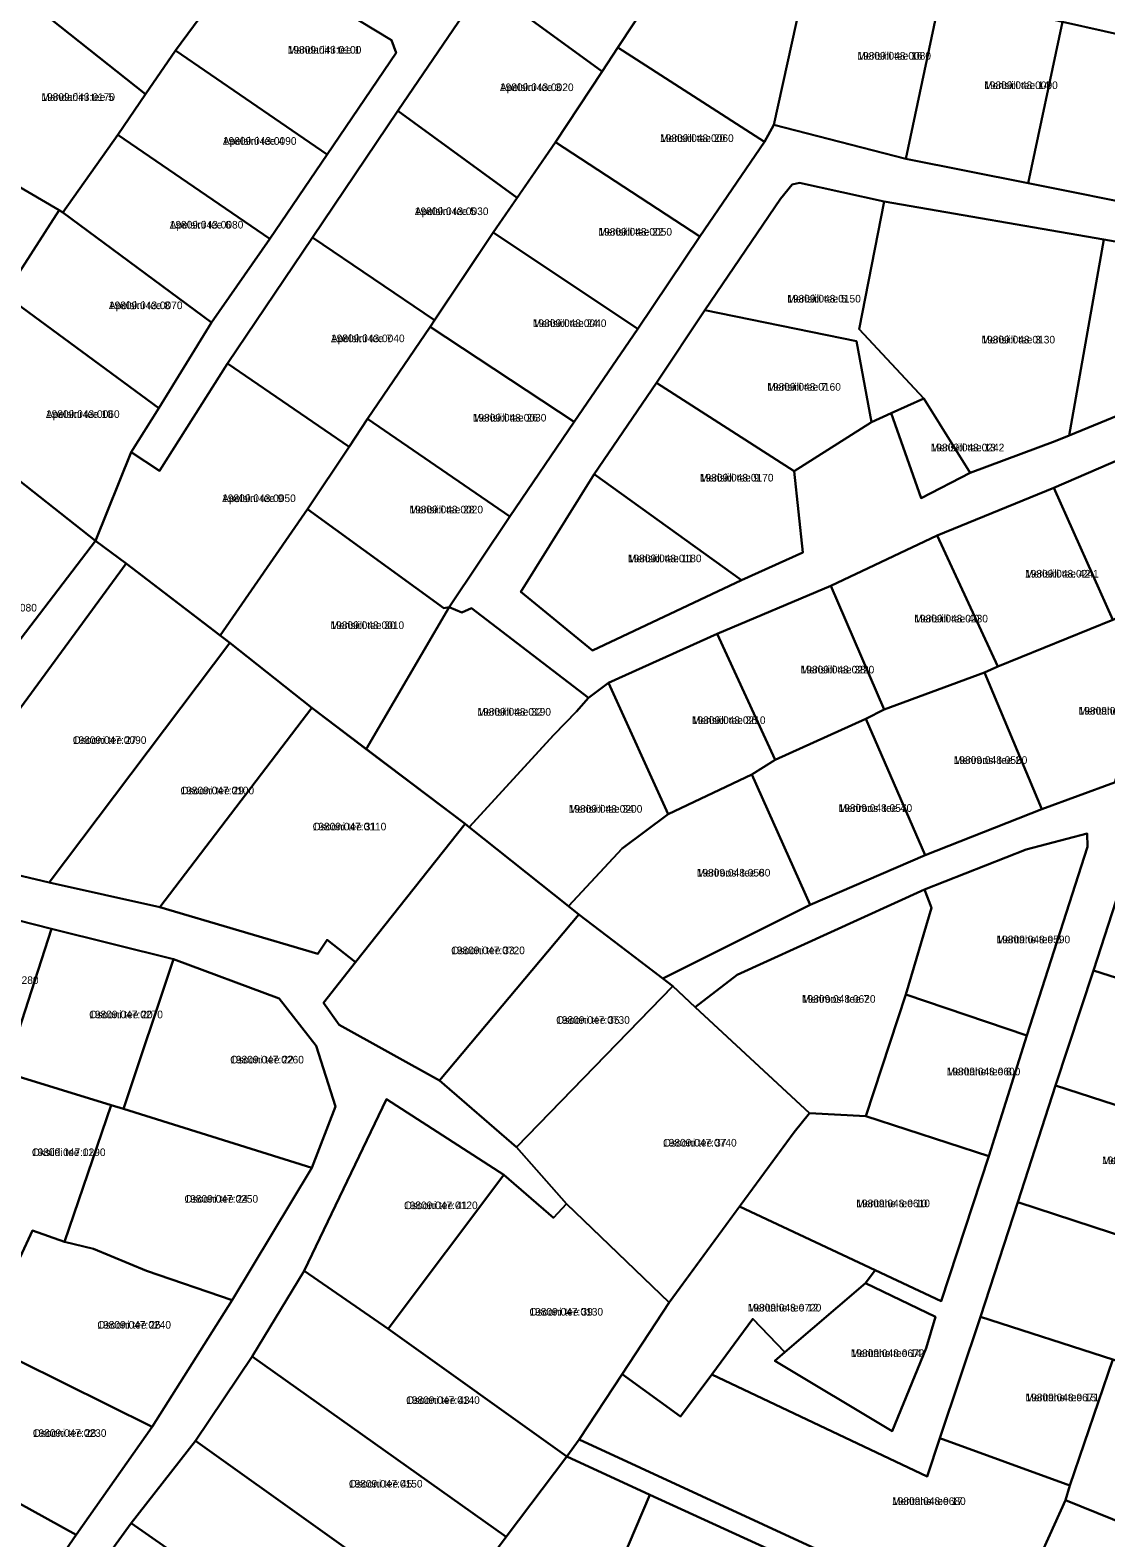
# Model space of a CAD drawing. Extents: x 516875 to 535633, y 6574491 to 6593094.
# Drawn here: x 522021.7 to 522233.5, y 6588097.9 to 6588394.7 of the extents above; entities that cross this region are included whole.
import ezdxf

# ---------------------------------------------------------------- set-up
doc = ezdxf.new("R2010")
doc.units = 0
for name, color, linetype in [('L_AADRESS', 7, 'Continuous'), ('PIIR', 7, 'Continuous'), ('TUNNUS', 7, 'Continuous')]:
    doc.layers.add(name, color=color, linetype=linetype)

msp = doc.modelspace()

# ---------------------------------------------------------------- linework, layer by layer
at = {"layer": 'PIIR'}
for points in [[(522152.8, 6588414.65), (522137.34, 6588391.3), (522134.27, 6588386.61), (522110.91, 6588403.64), (522127.24, 6588429.4)], [(522033.23, 6588412.68), (522040.61, 6588415.96), (522050.21, 6588417.4), (522064.48, 6588409.93), (522050.26, 6588390.69), (522044.38, 6588382.1), (522018.39, 6588402.82)], [(522175.18, 6588408.28), (522168.11, 6588376.06), (522166.24, 6588372.75), (522137.34, 6588391.3), (522152.8, 6588414.65)], [(522064.48, 6588409.93), (522092.78, 6588392.77), (522093.7, 6588390.23), (522080.13, 6588370.27), (522050.26, 6588390.69)], [(522200.95, 6588401.92), (522194.06, 6588369.42), (522168.11, 6588376.06), (522175.18, 6588408.28)], [(522006.88, 6588371.24), (522008.43, 6588373.57), (522002.04, 6588377.52), (522008, 6588386.5), (522004.6, 6588391.87), (522018.39, 6588402.82), (522044.38, 6588382.1), (522038.94, 6588374.15), (522028.11, 6588358.8), (522027.34, 6588359.31)], [(522094.05, 6588378.86), (522110.91, 6588403.64), (522134.27, 6588386.61), (522125.12, 6588372.66), (522117.54, 6588361.73)], [(522224.93, 6588396.36), (522218.17, 6588364.58), (522194.06, 6588369.42), (522200.95, 6588401.92)], [(522249.57, 6588390.88), (522243.06, 6588359.61), (522218.17, 6588364.58), (522224.93, 6588396.36)], [(522044.38, 6588382.1), (522050.26, 6588390.69), (522080.13, 6588370.27), (522068.88, 6588353.63), (522038.94, 6588374.15)], [(522166.24, 6588372.75), (522153.54, 6588354.12), (522125.12, 6588372.66), (522134.27, 6588386.61), (522137.34, 6588391.3)], [(522077.26, 6588353.91), (522094.05, 6588378.86), (522117.54, 6588361.73), (522112.82, 6588354.92), (522101.27, 6588337.6)], [(522038.94, 6588374.15), (522068.88, 6588353.63), (522057.37, 6588337.19), (522028.11, 6588358.8)], [(522153.54, 6588354.12), (522141.28, 6588335.9), (522112.82, 6588354.92), (522125.12, 6588372.66)], [(521982.14, 6588335.38), (522004.99, 6588368.24), (522006.88, 6588371.24), (522027.34, 6588359.31), (522016.7, 6588342.59), (522002.12, 6588319.68)], [(522132.7, 6588307.34), (522118.27, 6588284.12), (522132.35, 6588272.62), (522161.72, 6588286.42), (522173.79, 6588291.9), (522172.07, 6588307.93), (522187.34, 6588317.56), (522191.17, 6588319.3), (522197.1, 6588302.61), (522206.77, 6588307.61), (522223.48, 6588313.81), (522226.22, 6588314.93), (522260.43, 6588328.94), (522264.83, 6588347.96), (522233.05, 6588353.51), (522189.84, 6588360.99), (522173.11, 6588364.66), (522171.69, 6588364.32), (522169.41, 6588361.54), (522154.49, 6588339.57), (522144.96, 6588325.31)], [(522169.41, 6588361.54), (522171.69, 6588364.32), (522173.11, 6588364.66), (522189.84, 6588360.99), (522184.87, 6588335.85), (522197.6, 6588322.22), (522191.17, 6588319.3), (522187.34, 6588317.56), (522184.34, 6588333.53), (522154.49, 6588339.57)], [(522233.05, 6588353.51), (522226.22, 6588314.93), (522223.48, 6588313.81), (522206.77, 6588307.61), (522197.6, 6588322.22), (522184.87, 6588335.85), (522189.84, 6588360.99)], [(522027.34, 6588359.31), (522028.11, 6588358.8), (522057.37, 6588337.19), (522046.97, 6588320.29), (522016.7, 6588342.59)], [(522060.5, 6588329.11), (522077.26, 6588353.91), (522101.27, 6588337.6), (522100.44, 6588336.34), (522088.1, 6588318.24), (522084.44, 6588312.72)], [(522141.28, 6588335.9), (522128.75, 6588317.63), (522100.44, 6588336.34), (522112.82, 6588354.92)], [(522264.83, 6588347.96), (522260.43, 6588328.94), (522226.22, 6588314.93), (522233.05, 6588353.51)], [(522016.7, 6588342.59), (522046.97, 6588320.29), (522041.55, 6588311.63), (522034.49, 6588294.19), (522015.34, 6588309.29), (522002.12, 6588319.68)], [(522184.34, 6588333.53), (522187.34, 6588317.56), (522172.07, 6588307.93), (522144.96, 6588325.31), (522154.49, 6588339.57)], [(522128.75, 6588317.63), (522116.08, 6588299.01), (522088.1, 6588318.24), (522100.44, 6588336.34)], [(522041.55, 6588311.63), (522047.14, 6588308), (522060.5, 6588329.11), (522084.44, 6588312.72), (522076.28, 6588300.44), (522059.06, 6588275.58), (522040.58, 6588289.75), (522034.49, 6588294.19)], [(522172.07, 6588307.93), (522173.79, 6588291.9), (522161.72, 6588286.42), (522132.7, 6588307.34), (522144.96, 6588325.31)], [(522197.6, 6588322.22), (522206.77, 6588307.61), (522197.1, 6588302.61), (522191.17, 6588319.3)], [(522116.08, 6588299.01), (522104.18, 6588281.14), (522103.13, 6588280.96), (522076.28, 6588300.44), (522084.44, 6588312.72), (522088.1, 6588318.24)], [(522255.64, 6588313.9), (522246.62, 6588283.32), (522244.6, 6588282.7), (522234.84, 6588278.67), (522223.2, 6588304.62), (522252.05, 6588317.08)], [(522034.49, 6588294.19), (521994.15, 6588241.44), (521982.51, 6588259.22), (521982.46, 6588266.63), (522015.34, 6588309.29)], [(522132.7, 6588307.34), (522161.72, 6588286.42), (522132.35, 6588272.62), (522118.27, 6588284.12)], [(522234.84, 6588278.67), (522212.17, 6588269.45), (522200.25, 6588295.23), (522223.2, 6588304.62)], [(522103.13, 6588280.96), (522104.18, 6588281.14), (522087.84, 6588253.21), (522077.1, 6588261.34), (522061, 6588274.09), (522059.06, 6588275.58), (522076.28, 6588300.44)], [(522212.17, 6588269.45), (522209.58, 6588268.26), (522189.83, 6588260.99), (522179.31, 6588285.33), (522200.25, 6588295.23)], [(522061, 6588274.09), (522025.42, 6588226.93), (521999.1, 6588233.14), (522040.58, 6588289.75)], [(522189.83, 6588260.99), (522186.18, 6588259.15), (522168.35, 6588251.09), (522156.9, 6588275.88), (522179.31, 6588285.33)], [(522212.17, 6588269.45), (522234.84, 6588278.67), (522244.6, 6588282.7), (522246.62, 6588283.32), (522241.95, 6588268.51), (522235.19, 6588246.62), (522220.83, 6588241.4), (522209.58, 6588268.26)], [(522131.57, 6588263.27), (522129.24, 6588260.58), (522124.74, 6588256.01), (522108.13, 6588237.82), (522107.34, 6588238.45), (522087.84, 6588253.21), (522104.18, 6588281.14), (522106.68, 6588280.08), (522108.54, 6588280.91)], [(522077.1, 6588261.34), (522047.22, 6588222.1), (522025.42, 6588226.93), (522061, 6588274.09)], [(522168.35, 6588251.09), (522163.76, 6588248.18), (522147.26, 6588240.41), (522135.54, 6588266.24), (522156.9, 6588275.88)], [(522189.83, 6588260.99), (522209.58, 6588268.26), (522220.83, 6588241.4), (522197.91, 6588232.32), (522186.18, 6588259.15)], [(522147.26, 6588240.41), (522138.22, 6588233.62), (522127.64, 6588222.27), (522108.13, 6588237.82), (522124.74, 6588256.01), (522129.24, 6588260.58), (522131.57, 6588263.27), (522135.54, 6588266.24)], [(522107.34, 6588238.45), (522085.74, 6588211.23), (522080.11, 6588215.65), (522078.33, 6588212.86), (522047.22, 6588222.1), (522077.1, 6588261.34)], [(522168.35, 6588251.09), (522186.18, 6588259.15), (522197.91, 6588232.32), (522175.23, 6588222.53), (522163.76, 6588248.18)], [(522138.22, 6588233.62), (522147.26, 6588240.41), (522163.76, 6588248.18), (522175.23, 6588222.53), (522146.2, 6588208.03), (522129.68, 6588220.65), (522127.64, 6588222.27)], [(522129.68, 6588220.65), (522102.27, 6588187.96), (522082.51, 6588198.91), (522079.44, 6588203.24), (522085.74, 6588211.23), (522107.34, 6588238.45), (522108.13, 6588237.82), (522127.64, 6588222.27)], [(522217.79, 6588233.4), (522229.79, 6588236.58), (522229.82, 6588233.97), (522217.9, 6588196.82), (522194.05, 6588204.89), (522199.12, 6588221.96), (522197.78, 6588225.57)], [(522264.52, 6588225.6), (522256.75, 6588201.43), (522231.06, 6588209.59), (522239.11, 6588234.54)], [(522025.87, 6588217.8), (522016.71, 6588189.53), (522015.02, 6588189.79), (521991.75, 6588197.28), (521998.77, 6588224.68)], [(522160.84, 6588208.77), (522197.78, 6588225.57), (522199.12, 6588221.96), (522194.05, 6588204.89), (522186.19, 6588180.95), (522175.11, 6588181.52), (522152.6, 6588202.41)], [(522148.19, 6588206.51), (522117.44, 6588174.86), (522102.27, 6588187.96), (522129.68, 6588220.65)], [(522049.87, 6588211.85), (522040.05, 6588182.35), (522037.62, 6588183.1), (522016.71, 6588189.53), (522025.87, 6588217.8)], [(522070.67, 6588204.07), (522077.96, 6588194.8), (522081.76, 6588182.84), (522077.15, 6588170.76), (522040.05, 6588182.35), (522049.87, 6588211.85)], [(522256.75, 6588201.43), (522249.29, 6588178.66), (522223.53, 6588187), (522231.06, 6588209.59)], [(522175.11, 6588181.52), (522172.07, 6588177.81), (522147.45, 6588144.23), (522127.23, 6588163.69), (522117.44, 6588174.86), (522148.19, 6588206.51), (522152.6, 6588202.41)], [(522217.9, 6588196.82), (522210.4, 6588173.05), (522186.19, 6588180.95), (522194.05, 6588204.89)], [(522016.71, 6588189.53), (522037.62, 6588183.1), (522028.41, 6588156.16), (522022.09, 6588158.45), (522019.69, 6588153.15), (522006.38, 6588159.24), (522015.02, 6588189.79)], [(522114.9, 6588169.41), (522092.18, 6588139.05), (522075.63, 6588150.46), (522091.83, 6588184.31)], [(522249.29, 6588178.66), (522241.75, 6588155.97), (522238.21, 6588156.8), (522216.11, 6588164.03), (522223.53, 6588187)], [(522040.05, 6588182.35), (522077.15, 6588170.76), (522061.45, 6588144.69), (522044.54, 6588150.49), (522034.11, 6588154.83), (522028.41, 6588156.16), (522037.62, 6588183.1)], [(522186.19, 6588180.95), (522210.4, 6588173.05), (522201.03, 6588144.5), (522188.03, 6588150.64), (522161.3, 6588163.12), (522172.07, 6588177.81), (522175.11, 6588181.52)], [(522124.73, 6588160.89), (522127.23, 6588163.69), (522147.45, 6588144.23), (522138.23, 6588130.17), (522129.78, 6588117.27), (522127.32, 6588113.93), (522092.18, 6588139.05), (522114.9, 6588169.41)], [(522238.21, 6588156.8), (522241.75, 6588155.97), (522267.45, 6588147.22), (522260.42, 6588125.68), (522257.32, 6588125.93), (522234.84, 6588133), (522208.79, 6588141.4), (522216.11, 6588164.03)], [(522188.03, 6588150.64), (522186.11, 6588148.07), (522170.22, 6588134.49), (522163.95, 6588141.03), (522155.87, 6588130.09), (522149.7, 6588121.84), (522138.23, 6588130.17), (522147.45, 6588144.23), (522161.3, 6588163.12)], [(522028.41, 6588156.16), (522034.11, 6588154.83), (522044.54, 6588150.49), (522061.45, 6588144.69), (522045.71, 6588119.75), (522010.71, 6588137.12), (522018.22, 6588150), (522019.69, 6588153.15), (522022.09, 6588158.45)], [(522092.18, 6588139.05), (522127.32, 6588113.93), (522115.41, 6588098.09), (522065.34, 6588133.64), (522075.63, 6588150.46)], [(522199.93, 6588141.45), (522198.07, 6588135.24), (522191.41, 6588118.94), (522168.26, 6588132.78), (522170.22, 6588134.49), (522186.11, 6588148.07)], [(522234.84, 6588133), (522226.35, 6588108.22), (522200.79, 6588117.55), (522208.79, 6588141.4)], [(522045.71, 6588119.75), (522030.73, 6588098.49), (521999.11, 6588115.98), (522000.79, 6588119.34), (522010.71, 6588137.12)], [(522115.41, 6588098.09), (522103.31, 6588082), (522054.22, 6588117.03), (522065.34, 6588133.64)], [(522257.32, 6588125.93), (522260.42, 6588125.68), (522250.51, 6588095.21), (522225.49, 6588105.33), (522226.35, 6588108.22), (522234.84, 6588133)], [(522149.7, 6588121.84), (522155.87, 6588130.09), (522198.27, 6588109.97), (522200.79, 6588117.55), (522226.35, 6588108.22), (522225.49, 6588105.33), (522213.47, 6588078.63), (522129.78, 6588117.27), (522138.23, 6588130.17)], [(522103.31, 6588082), (522091.23, 6588066.09), (522089.56, 6588067.27), (522041.53, 6588100.82), (522054.22, 6588117.03)], [(522030.73, 6588098.49), (522015.31, 6588076.21), (521986.11, 6588096.1), (521987.51, 6588098.39), (521996.37, 6588111.18), (521999.11, 6588115.98)], [(522143.64, 6588106.38), (522126.74, 6588066.59), (522100.63, 6588077.88), (522103.31, 6588082), (522115.41, 6588098.09), (522127.32, 6588113.93)], [(522143.64, 6588106.38), (522166.8, 6588095.85), (522149.73, 6588056.5), (522126.74, 6588066.59)], [(522250.51, 6588095.21), (522253.6, 6588093.82), (522244.48, 6588064.28), (522213.47, 6588078.63), (522225.49, 6588105.33)], [(522089.56, 6588067.27), (522077.12, 6588050.77), (522030.44, 6588085.53), (522041.53, 6588100.82)]]:
    msp.add_lwpolyline(points, close=True, dxfattribs=at)
for points in [[(522110.91, 6588403.64), (522094.05, 6588378.86), (522077.26, 6588353.91), (522060.5, 6588329.11), (522047.14, 6588308), (522041.55, 6588311.63), (522046.97, 6588320.29), (522057.37, 6588337.19), (522068.88, 6588353.63), (522080.13, 6588370.27), (522093.7, 6588390.23), (522092.78, 6588392.77), (522064.48, 6588409.93)], [(522249.57, 6588390.88), (522224.93, 6588396.36)], [(522252.05, 6588317.08), (522223.2, 6588304.62), (522200.25, 6588295.23), (522179.31, 6588285.33), (522156.9, 6588275.88), (522135.54, 6588266.24), (522131.57, 6588263.27), (522108.54, 6588280.91), (522106.68, 6588280.08), (522104.18, 6588281.14), (522116.08, 6588299.01), (522128.75, 6588317.63), (522141.28, 6588335.9), (522153.54, 6588354.12), (522166.24, 6588372.75), (522168.11, 6588376.06), (522194.06, 6588369.42), (522218.17, 6588364.58), (522243.06, 6588359.61)], [(521994.15, 6588241.44), (522034.49, 6588294.19), (522040.58, 6588289.75), (521999.1, 6588233.14), (522025.42, 6588226.93), (522047.22, 6588222.1), (522078.33, 6588212.86), (522080.11, 6588215.65), (522085.74, 6588211.23), (522079.44, 6588203.24), (522082.51, 6588198.91), (522102.27, 6588187.96), (522117.44, 6588174.86), (522127.23, 6588163.69), (522124.73, 6588160.89), (522114.9, 6588169.41), (522091.83, 6588184.31), (522075.63, 6588150.46), (522065.34, 6588133.64), (522054.22, 6588117.03), (522041.53, 6588100.82), (522030.44, 6588085.53)], [(522239.11, 6588234.54), (522231.06, 6588209.59), (522223.53, 6588187), (522216.11, 6588164.03), (522208.79, 6588141.4), (522200.79, 6588117.55), (522198.27, 6588109.97), (522155.87, 6588130.09), (522163.95, 6588141.03), (522170.22, 6588134.49), (522168.26, 6588132.78), (522191.41, 6588118.94), (522198.07, 6588135.24), (522199.93, 6588141.45), (522186.11, 6588148.07), (522188.03, 6588150.64), (522201.03, 6588144.5), (522210.4, 6588173.05), (522217.9, 6588196.82), (522229.82, 6588233.97), (522229.79, 6588236.58), (522217.79, 6588233.4), (522197.78, 6588225.57), (522160.84, 6588208.77), (522152.6, 6588202.41), (522148.19, 6588206.51), (522146.2, 6588208.03), (522175.23, 6588222.53), (522197.91, 6588232.32), (522220.83, 6588241.4), (522235.19, 6588246.62)], [(522015.31, 6588076.21), (522030.73, 6588098.49), (522045.71, 6588119.75), (522061.45, 6588144.69), (522077.15, 6588170.76), (522081.76, 6588182.84), (522077.96, 6588194.8), (522070.67, 6588204.07), (522049.87, 6588211.85), (522025.87, 6588217.8), (521998.77, 6588224.68), (521965.79, 6588221.88), (521954.83, 6588217.23), (521937.53, 6588201.19), (521922.82, 6588181.22), (521909.42, 6588162.67), (521895.72, 6588144.67), (521882.77, 6588125.18), (521864.91, 6588102.09), (521893.34, 6588086.36)], [(522235.1, 6588065.06), (522212.08, 6588075.43), (522189.38, 6588085.67), (522166.8, 6588095.85), (522143.64, 6588106.38), (522127.32, 6588113.93), (522129.78, 6588117.27), (522213.47, 6588078.63), (522244.48, 6588064.28)]]:
    msp.add_lwpolyline(points, dxfattribs=at)

# ---------------------------------------------------------------- texts
at = {"layer": 'L_AADRESS'}
for s, p in [('Mandariini tee 1', (522072.37, 6588390.1)), ('Merisiili tee 16', (522184.53, 6588388.92)), ('Apelsini tee 3', (522114.16, 6588382.73)), ('Merisiili tee 14', (522209.5, 6588383.13)), ('Mandariini tee 5', (522023.86, 6588380.81)), ('Merisiili tee 20', (522145.68, 6588372.71)), ('Apelsini tee 4', (522059.6, 6588372.16)), ('Apelsini tee 5', (522097.4, 6588358.32)), ('Apelsini tee 6', (522049.13, 6588355.67)), ('Merisiili tee 22', (522133.54, 6588354.28)), ('Merisiili tee 5', (522170.72, 6588341.11)), ('Apelsini tee 8', (522037.16, 6588339.8)), ('Merisiili tee 24', (522120.63, 6588336.28)), ('Apelsini tee 7', (522080.89, 6588333.3)), ('Merisiili tee 3', (522208.96, 6588333.05)), ('Merisiili tee 7', (522166.79, 6588323.75)), ('Apelsini tee 10', (522024.77, 6588318.39)), ('Merisiili tee 26', (522108.8, 6588317.68)), ('Merisiili tee 13', (522198.97, 6588311.81)), ('Merisiili tee 9', (522153.52, 6588305.87)), ('Apelsini tee 9', (522059.46, 6588301.82)), ('Merisiili tee 28', (522096.33, 6588299.6)), ('Merisiili tee 11', (522139.35, 6588289.98)), ('Merisiili tee 42', (522217.55, 6588286.97)), ('Merisiili tee 40', (522195.74, 6588278.13)), ('Merisiili tee 30', (522080.79, 6588276.83)), ('Merisiili tee 38', (522173.36, 6588268.09)), ('Meritähe tee 4', (522228.1, 6588259.99)), ('Merisiili tee 32', (522109.71, 6588259.78)), ('Merisiili tee 36', (522151.95, 6588258.13)), ('Osooni tee 27', (522030.05, 6588254.22)), ('Meriroosi tee 2', (522203.5, 6588250.28)), ('Osooni tee 29', (522051.26, 6588244.29)), ('Merisiili tee 34', (522127.7, 6588240.67)), ('Meriroosi tee 4', (522180.83, 6588240.84)), ('Osooni tee 31', (522077.28, 6588237.19)), ('Meriroosi tee 6', (522152.91, 6588228.11)), ('Osooni tee 33', (522104.56, 6588212.82)), ('Meritähe tee 6', (522211.93, 6588214.97)), ('Meriroosi tee 7', (522173.61, 6588203.26)), ('Osooni tee 20', (522033.29, 6588200.2)), ('Osooni tee 35', (522125.23, 6588199.11)), ('Osooni tee 22', (522061.05, 6588191.31)), ('Meritähe tee 8', (522202.12, 6588188.97)), ('Osooni tee 37', (522146.27, 6588174.95)), ('Oksiidi tee 11', (522022, 6588173.08)), ('Meritähe tee 11', (522232.71, 6588171.49)), ('Osooni tee 24', (522052.04, 6588163.9)), ('Osooni tee 41', (522095.27, 6588162.63)), ('Meritähe tee 10', (522184.32, 6588163.01)), ('Osooni tee 39', (522119.96, 6588141.67)), ('Meritähe tee 12', (522162.94, 6588142.48)), ('Osooni tee 26', (522034.89, 6588139.1)), ('Meritähe tee 14', (522183.23, 6588133.51)), ('Osooni tee 43', (522095.69, 6588124.28)), ('Meritähe tee 15', (522217.63, 6588124.81)), ('Osooni tee 28', (522022.18, 6588117.8)), ('Osooni tee 45', (522084.42, 6588107.82)), ('Meritähe tee 17', (522191.36, 6588104.4))]:
    msp.add_text(s, height=1.5, dxfattribs=at).set_placement(p)
at = {"layer": 'TUNNUS'}
for s, p in [('19809:043:0100', (522072.37, 6588390.1)), ('19809:048:0080', (522184.53, 6588388.92)), ('19809:043:0020', (522114.16, 6588382.73)), ('19809:048:0090', (522209.5, 6588383.13)), ('19809:043:0170', (522023.86, 6588380.81)), ('19809:043:0090', (522059.6, 6588372.16)), ('19809:048:0060', (522145.68, 6588372.71)), ('19809:043:0030', (522097.4, 6588358.32)), ('19809:043:0080', (522049.13, 6588355.67)), ('19809:048:0050', (522133.54, 6588354.28)), ('19809:048:0150', (522170.72, 6588341.11)), ('19809:043:0070', (522037.16, 6588339.8)), ('19809:048:0040', (522120.63, 6588336.28)), ('19809:043:0040', (522080.89, 6588333.3)), ('19809:048:0130', (522208.96, 6588333.05)), ('19809:048:0160', (522166.79, 6588323.75)), ('19809:043:0060', (522024.77, 6588318.39)), ('19809:048:0030', (522108.8, 6588317.68)), ('19809:048:0242', (522198.97, 6588311.81)), ('19809:048:0170', (522153.52, 6588305.87)), ('19809:043:0050', (522059.46, 6588301.82)), ('19809:048:0020', (522096.33, 6588299.6)), ('19809:048:0180', (522139.35, 6588289.98)), ('19809:048:0241', (522217.55, 6588286.97)), ('19809:047:0080', (522008.48, 6588280.28)), ('19809:048:0230', (522195.74, 6588278.13)), ('19809:048:0010', (522080.79, 6588276.83)), ('19809:048:0220', (522173.36, 6588268.09)), ('19809:048:0550', (522228.1, 6588259.99)), ('19809:048:0190', (522109.71, 6588259.78)), ('19809:048:0210', (522151.95, 6588258.13)), ('19809:047:0090', (522030.05, 6588254.22)), ('19809:048:0560', (522203.5, 6588250.28)), ('19809:047:0100', (522051.26, 6588244.29)), ('19809:048:0200', (522127.7, 6588240.67)), ('19809:048:0570', (522180.83, 6588240.84)), ('19809:047:0110', (522077.28, 6588237.19)), ('19809:048:0580', (522152.91, 6588228.11)), ('19809:047:0720', (522104.56, 6588212.82)), ('19809:048:0590', (522211.93, 6588214.97)), ('19809:047:0280', (522008.81, 6588206.96)), ('19809:048:0620', (522173.61, 6588203.26)), ('19809:047:0270', (522033.29, 6588200.2)), ('19809:047:0730', (522125.23, 6588199.11)), ('19809:047:0260', (522061.05, 6588191.31)), ('19809:048:0600', (522202.12, 6588188.97)), ('19809:047:0740', (522146.27, 6588174.95)), ('19809:047:0290', (522022, 6588173.08)), ('19809:048:0650', (522232.71, 6588171.49)), ('19809:047:0250', (522052.04, 6588163.9)), ('19809:047:0120', (522095.27, 6588162.63)), ('19809:048:0610', (522184.32, 6588163.01)), ('19809:047:0130', (522119.96, 6588141.67)), ('19809:048:0720', (522162.94, 6588142.48)), ('19809:047:0240', (522034.89, 6588139.1)), ('19809:048:0672', (522183.23, 6588133.51)), ('19809:047:0140', (522095.69, 6588124.28)), ('19809:048:0671', (522217.63, 6588124.81)), ('19809:047:0230', (522022.18, 6588117.8)), ('19809:047:0150', (522084.42, 6588107.82)), ('19809:048:0680', (522191.36, 6588104.4))]:
    msp.add_text(s, height=1.5, dxfattribs=at).set_placement(p)

doc.saveas('drawing.dxf')
